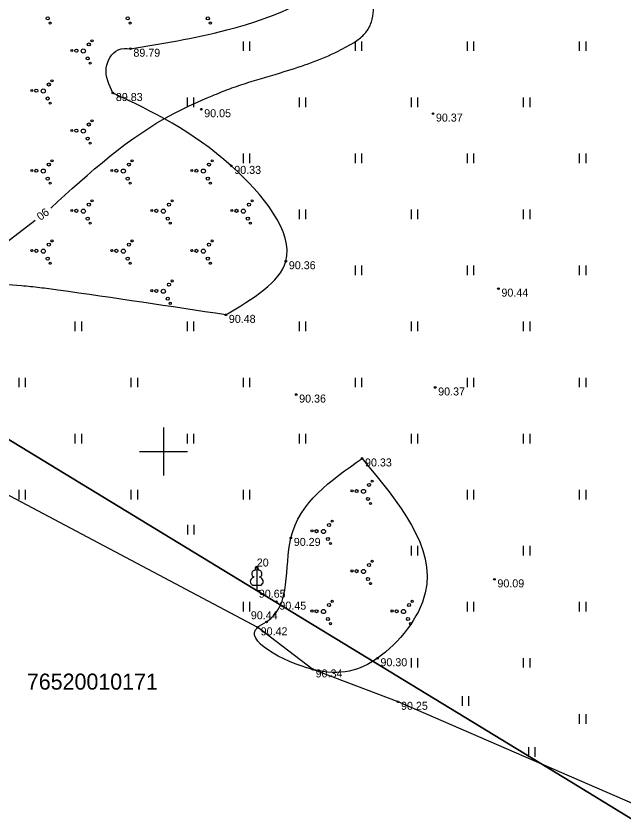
# Model space of a CAD drawing. Extents: x 635228 to 635525, y 248590 to 248800.
# Drawn here: x 635340.8 to 635378.8, y 248626.9 to 248677.2 of the extents above; entities that cross this region are included whole.
import ezdxf

# ---------------------------------------------------------------- set-up
doc = ezdxf.new("R2010")
doc.units = 0
for name, color, linetype in [('GEOD_ELEM_####_####_#', 7, 'Continuous'), ('RAMI_UZMR_####_####_#', 7, 'Continuous'), ('RELJ_AATZ_####_TKST_#', 7, 'Continuous'), ('RELJ_ELEM_####_####_#', 7, 'Continuous'), ('RELJ_HORZ_####_TKST_#', 7, 'Continuous'), ('RELJ_HORZ_RESN_####_#', 7, 'Continuous'), ('RELJ_NOGA_####_####_#', 7, 'Continuous'), ('RELJ_NOGL_####_####_#', 7, 'Continuous'), ('ROBZ_UZMR_####_####_#', 7, 'Continuous'), ('ROBZ_UZMR_####_TKST_#', 7, 'Continuous'), ('TERT_DIAM_####_TKST_#', 7, 'Continuous'), ('TERT_ELEM_####_####_#', 7, 'Continuous'), ('TERT_KONT_####_####_#', 7, 'Continuous')]:
    doc.layers.add(name, color=color, linetype=linetype)

msp = doc.modelspace()

# ---------------------------------------------------------------- linework, layer by layer
at = {"layer": 'GEOD_ELEM_####_####_#'}
for p, q in [((635350, 248651.5), (635350, 248650)), ((635348.5, 248650), (635350, 248650)), ((635350, 248650), (635350, 248648.5)), ((635350, 248650), (635351.5, 248650))]:
    msp.add_line(p, q, dxfattribs=at)
at = {"layer": 'RAMI_UZMR_####_####_#'}
msp.add_lwpolyline([(635379.918, 248627.738), (635364.657, 248634.365), (635359.326, 248636.387), (635355.893, 248639.014), (635323.971, 248655.917), (635326.8, 248663.851), (635331.354, 248676.262), (635327.703, 248680.035), (635326.374, 248681.182), (635325.201, 248682.696), (635327.977, 248685.285), (635332.779, 248692.762), (635338.144, 248706.864), (635340.529, 248716.56), (635346.791, 248738.298), (635351.394, 248755.812), (635352.126, 248761.775)], dxfattribs=at)
at = {"layer": 'RELJ_ELEM_####_####_#'}
for centre in [(635347.944, 248675.14), (635346.848, 248672.375), (635352.366, 248671.364), (635366.837, 248671.092), (635354.244, 248667.827), (635357.651, 248661.873), (635370.928, 248660.162), (635353.903, 248658.524), (635366.978, 248653.992), (635358.297, 248653.548), (635362.409, 248649.56), (635357.961, 248644.598), (635370.678, 248642.01), (635357.062, 248640.618), (635356.442, 248639.354), (635355.893, 248639.014), (635363.372, 248637.085), (635359.326, 248636.387), (635364.657, 248634.365)]:
    msp.add_circle(centre, 0.05, dxfattribs=at)
at = {"layer": 'RELJ_HORZ_RESN_####_#'}
msp.add_line((635328.081, 248653.741), (635341.998, 248664.444), dxfattribs=at)
msp.add_spline([(635342.967, 248665.189), (635350.649, 248671.097), (635353.044, 248672.199), (635354.147, 248672.641), (635355.27, 248673.022), (635357.544, 248673.711), (635360.916, 248674.993), (635361.461, 248675.281), (635362, 248675.6), (635362.585, 248676.091), (635362.941, 248676.666), (635363.082, 248678.034), (635362.825, 248678.873), (635362.542, 248679.71), (635361.896, 248681.359), (635361.504, 248682.258), (635361.094, 248683.142), (635360.687, 248684.033), (635360.306, 248684.949), (635359.942, 248686.647), (635360.049, 248687.813), (635360.176, 248688.176), (635361.529, 248691.159), (635363.072, 248694.104), (635364.881, 248696.95), (635367.032, 248699.635), (635368.378, 248700.848), (635369.286, 248701.486)], degree=3, dxfattribs=at)
at = {"layer": 'RELJ_NOGA_####_####_#'}
for points in [[(635375.27, 248754.857), (635369.314, 248744.971), (635367.429, 248741.507), (635365.696, 248737.957), (635363.943, 248734.417), (635363.006, 248732.681), (635362, 248730.984), (635361.355, 248730.103), (635360.628, 248729.283), (635359.885, 248728.474), (635359.193, 248727.625), (635357.58, 248725.368), (635356.018, 248723.079), (635353.089, 248718.349), (635349.569, 248710.638), (635349.163, 248709.221), (635348.864, 248707.772), (635348.539, 248706.335), (635348.053, 248704.954), (635343.12, 248694.162), (635337.407, 248681.667), (635331.093, 248670.147), (635326.8, 248663.851)], [(635326.8, 248663.851), (635325.31, 248661.345), (635325.174, 248660.918), (635325.219, 248660.451), (635325.416, 248659.984), (635325.736, 248659.553), (635326.126, 248659.27), (635326.575, 248659.146), (635327.409, 248659.333), (635327.907, 248659.688), (635328.397, 248660.078), (635328.864, 248660.506), (635329.288, 248660.978), (635331.594, 248663.918), (635332.687, 248665.412), (635333.734, 248666.95), (635337.875, 248673.353), (635341.554, 248680.001), (635347.428, 248693.006), (635353.063, 248706.101), (635354.098, 248708.621), (635355.097, 248711.155), (635356.117, 248713.682), (635356.653, 248714.935), (635357.216, 248716.179), (635358.916, 248719.218), (635360.822, 248722.14), (635362.339, 248724.363), (635363.916, 248726.545), (635365.467, 248728.744), (635366.906, 248731.015), (635368.464, 248733.981), (635369.863, 248737.03), (635371.249, 248740.086), (635372.769, 248743.072), (635378.435, 248753.196)]]:
    msp.add_spline(points, degree=3, dxfattribs=at)
at = {"layer": 'RELJ_NOGL_####_####_#'}
msp.add_spline([(635326.936, 248660.713), (635331.766, 248667.928), (635333.88, 248671.254), (635335.853, 248674.668), (635337.706, 248678.153), (635339.464, 248681.691), (635342.12, 248687.391), (635344.65, 248693.14), (635347.108, 248698.916), (635349.548, 248704.698), (635350.777, 248707.84), (635351.91, 248711.022), (635353.067, 248714.195), (635353.692, 248715.764), (635354.368, 248717.312), (635355.034, 248718.536), (635355.835, 248719.677), (635357.677, 248721.811), (635359.567, 248723.919), (635361.176, 248726.206), (635362.355, 248728.434), (635362.939, 248729.551), (635363.546, 248730.656), (635367.422, 248737.348), (635371.307, 248744.035), (635372.506, 248746.487), (635373.579, 248749.023), (635374.785, 248751.459), (635376.384, 248753.612), (635376.807, 248754.05)], degree=3, dxfattribs=at)
at = {"layer": 'ROBZ_UZMR_####_####_#'}
msp.add_lwpolyline([(635325.542, 248659.74), (635329.653, 248676.366), (635327.79, 248676.828), (635337.46, 248688.66), (635343.343, 248703.12), (635360.483, 248762.615), (635458.607, 248711.134), (635465.459, 248707.539), (635439.457, 248681.038), (635424.543, 248670.014), (635420.979, 248667.379), (635407.07, 248653.18), (635400.067, 248641.149), (635395.162, 248617.539), (635389.031, 248621.062), (635375.858, 248629.115)], close=True, dxfattribs=at)
msp.add_lwpolyline([(635385.967, 248592.676), (635383.57, 248593.46), (635239.492, 248640.545), (635247.631, 248661.649), (635302.855, 248630.558), (635325.542, 248659.74), (635375.858, 248629.115), (635389.031, 248621.062), (635395.162, 248617.539), (635393.88, 248601.96), (635390.766, 248592.676)], dxfattribs=at)
at = {"layer": 'TERT_ELEM_####_####_#'}
for p, q in [((635355, 248675), (635355, 248675.6)), ((635355.4, 248675), (635355.4, 248675.6)), ((635362, 248675), (635362, 248675.6)), ((635362.4, 248675), (635362.4, 248675.6)), ((635369, 248675), (635369, 248675.6)), ((635369.4, 248675), (635369.4, 248675.6)), ((635376, 248675), (635376, 248675.6)), ((635376.4, 248675), (635376.4, 248675.6)), ((635351.5, 248671.5), (635351.5, 248672.1)), ((635351.9, 248671.5), (635351.9, 248672.1)), ((635358.5, 248671.5), (635358.5, 248672.1)), ((635358.9, 248671.5), (635358.9, 248672.1)), ((635365.5, 248671.5), (635365.5, 248672.1)), ((635365.9, 248671.5), (635365.9, 248672.1)), ((635372.5, 248671.5), (635372.5, 248672.1)), ((635372.9, 248671.5), (635372.9, 248672.1)), ((635355, 248668), (635355, 248668.6)), ((635355.4, 248668), (635355.4, 248668.6)), ((635362, 248668), (635362, 248668.6)), ((635362.4, 248668), (635362.4, 248668.6)), ((635369, 248668), (635369, 248668.6)), ((635369.4, 248668), (635369.4, 248668.6)), ((635376, 248668), (635376, 248668.6)), ((635376.4, 248668), (635376.4, 248668.6)), ((635358.5, 248664.5), (635358.5, 248665.1)), ((635358.9, 248664.5), (635358.9, 248665.1)), ((635365.5, 248664.5), (635365.5, 248665.1)), ((635365.9, 248664.5), (635365.9, 248665.1)), ((635372.5, 248664.5), (635372.5, 248665.1)), ((635372.9, 248664.5), (635372.9, 248665.1)), ((635362, 248661), (635362, 248661.6)), ((635362.4, 248661), (635362.4, 248661.6)), ((635369, 248661), (635369, 248661.6)), ((635369.4, 248661), (635369.4, 248661.6)), ((635376, 248661), (635376, 248661.6)), ((635376.4, 248661), (635376.4, 248661.6)), ((635344.5, 248657.5), (635344.5, 248658.1)), ((635344.9, 248657.5), (635344.9, 248658.1)), ((635351.5, 248657.5), (635351.5, 248658.1)), ((635351.9, 248657.5), (635351.9, 248658.1)), ((635358.5, 248657.5), (635358.5, 248658.1)), ((635358.9, 248657.5), (635358.9, 248658.1)), ((635365.5, 248657.5), (635365.5, 248658.1)), ((635365.9, 248657.5), (635365.9, 248658.1)), ((635372.5, 248657.5), (635372.5, 248658.1)), ((635372.9, 248657.5), (635372.9, 248658.1)), ((635341, 248654), (635341, 248654.6)), ((635341.4, 248654), (635341.4, 248654.6)), ((635348, 248654), (635348, 248654.6)), ((635348.4, 248654), (635348.4, 248654.6)), ((635355, 248654), (635355, 248654.6)), ((635355.4, 248654), (635355.4, 248654.6)), ((635362, 248654), (635362, 248654.6)), ((635362.4, 248654), (635362.4, 248654.6)), ((635369, 248654), (635369, 248654.6)), ((635369.4, 248654), (635369.4, 248654.6)), ((635376, 248654), (635376, 248654.6)), ((635376.4, 248654), (635376.4, 248654.6)), ((635344.5, 248650.5), (635344.5, 248651.1)), ((635344.9, 248650.5), (635344.9, 248651.1)), ((635351.5, 248650.5), (635351.5, 248651.1)), ((635351.9, 248650.5), (635351.9, 248651.1)), ((635358.5, 248650.5), (635358.5, 248651.1)), ((635358.9, 248650.5), (635358.9, 248651.1)), ((635365.5, 248650.5), (635365.5, 248651.1)), ((635365.9, 248650.5), (635365.9, 248651.1)), ((635372.5, 248650.5), (635372.5, 248651.1)), ((635372.9, 248650.5), (635372.9, 248651.1)), ((635341, 248647), (635341, 248647.6)), ((635341.4, 248647), (635341.4, 248647.6)), ((635348, 248647), (635348, 248647.6)), ((635348.4, 248647), (635348.4, 248647.6)), ((635355, 248647), (635355, 248647.6)), ((635355.4, 248647), (635355.4, 248647.6)), ((635369, 248647), (635369, 248647.6)), ((635369.4, 248647), (635369.4, 248647.6)), ((635376, 248647), (635376, 248647.6)), ((635376.4, 248647), (635376.4, 248647.6)), ((635351.529, 248644.812), (635351.529, 248645.412)), ((635351.929, 248644.812), (635351.929, 248645.412)), ((635365.5, 248643.5), (635365.5, 248644.1)), ((635365.9, 248643.5), (635365.9, 248644.1)), ((635372.5, 248643.5), (635372.5, 248644.1)), ((635372.9, 248643.5), (635372.9, 248644.1)), ((635355.835, 248641.657), (635355.835, 248641.31)), ((635355.835, 248641.31), (635356.035, 248641.31)), ((635355, 248640), (635355, 248640.6)), ((635355.4, 248640), (635355.4, 248640.6)), ((635369, 248640), (635369, 248640.6)), ((635369.4, 248640), (635369.4, 248640.6)), ((635376, 248640), (635376, 248640.6)), ((635376.4, 248640), (635376.4, 248640.6)), ((635365.5, 248636.5), (635365.5, 248637.1)), ((635365.9, 248636.5), (635365.9, 248637.1)), ((635372.5, 248636.5), (635372.5, 248637.1)), ((635372.9, 248636.5), (635372.9, 248637.1)), ((635368.683, 248634.11), (635368.683, 248634.71)), ((635369.083, 248634.11), (635369.083, 248634.71)), ((635376, 248633), (635376, 248633.6)), ((635376.4, 248633), (635376.4, 248633.6)), ((635372.827, 248630.928), (635372.827, 248631.528)), ((635373.227, 248630.928), (635373.227, 248631.528))]:
    msp.add_line(p, q, dxfattribs=at)
for points in [[(635355.835, 248642.81), (635355.835, 248641.657)], [(635355.925, 248642.578), (635355.924, 248642.579)]]:
    msp.add_lwpolyline(points, dxfattribs=at)
for centre, radius in [((635342.776, 248677.033), 0.096), ((635347.776, 248677.033), 0.096), ((635352.776, 248677.033), 0.096), ((635342.934, 248676.744), 0.064), ((635347.934, 248676.744), 0.064), ((635352.934, 248676.744), 0.064), ((635345.544, 248675.639), 0.064), ((635344.282, 248675.034), 0.064), ((635344.566, 248675.021), 0.096), ((635345, 248675), 0.128), ((635345.348, 248675.408), 0.096), ((635345.276, 248674.533), 0.096), ((635345.434, 248674.244), 0.064), ((635343.044, 248673.139), 0.064), ((635341.782, 248672.534), 0.064), ((635342.066, 248672.521), 0.096), ((635342.5, 248672.5), 0.128), ((635342.848, 248672.908), 0.096), ((635342.776, 248672.033), 0.096), ((635342.934, 248671.744), 0.064), ((635345.544, 248670.639), 0.064), ((635344.282, 248670.034), 0.064), ((635344.566, 248670.021), 0.096), ((635345, 248670), 0.128), ((635345.348, 248670.408), 0.096), ((635345.276, 248669.533), 0.096), ((635345.434, 248669.244), 0.064), ((635343.044, 248668.139), 0.064), ((635348.044, 248668.139), 0.064), ((635353.044, 248668.139), 0.064), ((635341.782, 248667.534), 0.064), ((635342.066, 248667.521), 0.096), ((635342.5, 248667.5), 0.128), ((635342.848, 248667.908), 0.096), ((635346.782, 248667.534), 0.064), ((635347.066, 248667.521), 0.096), ((635347.5, 248667.5), 0.128), ((635347.848, 248667.908), 0.096), ((635351.782, 248667.534), 0.064), ((635352.066, 248667.521), 0.096), ((635352.5, 248667.5), 0.128), ((635352.848, 248667.908), 0.096), ((635342.776, 248667.033), 0.096), ((635347.776, 248667.033), 0.096), ((635352.776, 248667.033), 0.096), ((635342.934, 248666.744), 0.064), ((635347.934, 248666.744), 0.064), ((635352.934, 248666.744), 0.064), ((635345.544, 248665.639), 0.064), ((635350.544, 248665.639), 0.064), ((635355.544, 248665.639), 0.064), ((635344.282, 248665.034), 0.064), ((635344.566, 248665.021), 0.096), ((635345, 248665), 0.128), ((635345.348, 248665.408), 0.096), ((635349.282, 248665.034), 0.064), ((635349.566, 248665.021), 0.096), ((635350, 248665), 0.128), ((635350.348, 248665.408), 0.096), ((635354.282, 248665.034), 0.064), ((635354.566, 248665.021), 0.096), ((635355, 248665), 0.128), ((635355.348, 248665.408), 0.096), ((635345.276, 248664.533), 0.096), ((635350.276, 248664.533), 0.096), ((635355.276, 248664.533), 0.096), ((635345.434, 248664.244), 0.064), ((635350.434, 248664.244), 0.064), ((635355.434, 248664.244), 0.064), ((635343.044, 248663.139), 0.064), ((635348.044, 248663.139), 0.064), ((635353.044, 248663.139), 0.064), ((635341.782, 248662.534), 0.064), ((635342.066, 248662.521), 0.096), ((635342.5, 248662.5), 0.128), ((635342.848, 248662.908), 0.096), ((635346.782, 248662.534), 0.064), ((635347.066, 248662.521), 0.096), ((635347.5, 248662.5), 0.128), ((635347.848, 248662.908), 0.096), ((635351.782, 248662.534), 0.064), ((635352.066, 248662.521), 0.096), ((635352.5, 248662.5), 0.128), ((635352.848, 248662.908), 0.096), ((635342.776, 248662.033), 0.096), ((635347.776, 248662.033), 0.096), ((635352.776, 248662.033), 0.096), ((635342.934, 248661.744), 0.064), ((635347.934, 248661.744), 0.064), ((635352.934, 248661.744), 0.064), ((635350.544, 248660.639), 0.064), ((635349.282, 248660.034), 0.064), ((635349.566, 248660.021), 0.096), ((635350, 248660), 0.128), ((635350.348, 248660.408), 0.096), ((635350.276, 248659.533), 0.096), ((635350.434, 248659.244), 0.064), ((635362.848, 248647.908), 0.096), ((635363.044, 248648.139), 0.064), ((635361.782, 248647.534), 0.064), ((635362.066, 248647.521), 0.096), ((635362.5, 248647.5), 0.128), ((635362.776, 248647.033), 0.096), ((635362.934, 248646.744), 0.064), ((635360.348, 248645.408), 0.096), ((635360.544, 248645.639), 0.064), ((635359.282, 248645.034), 0.064), ((635359.566, 248645.021), 0.096), ((635360, 248645), 0.128), ((635360.276, 248644.533), 0.096), ((635360.434, 248644.244), 0.064), ((635362.848, 248642.908), 0.096), ((635363.044, 248643.139), 0.064), ((635361.782, 248642.534), 0.064), ((635362.066, 248642.521), 0.096), ((635362.5, 248642.5), 0.128), ((635362.776, 248642.033), 0.096), ((635362.934, 248641.744), 0.064), ((635360.348, 248640.408), 0.096), ((635360.544, 248640.639), 0.064), ((635365.348, 248640.408), 0.096), ((635365.544, 248640.639), 0.064), ((635359.282, 248640.034), 0.064), ((635359.566, 248640.021), 0.096), ((635360, 248640), 0.128), ((635364.282, 248640.034), 0.064), ((635364.566, 248640.021), 0.096), ((635365, 248640), 0.128), ((635360.276, 248639.533), 0.096), ((635365.276, 248639.533), 0.096), ((635360.434, 248639.244), 0.064), ((635365.434, 248639.244), 0.064)]:
    msp.add_circle(centre, radius, dxfattribs=at)
for centre, major_axis, ratio, start_param, end_param in [((635355.707, 248642.365), (-0.039, -0.212), 0.861323, 3.141593, 6.283185), ((635355.836, 248642.66), (0, -0.15), 0.707107, 3.14537, 5.287485), ((635355.835, 248642.66), (0, -0.15), 0.707107, 0.995701, 3.137816), ((635355.964, 248642.365), (0.039, -0.212), 0.861323, 0, 3.141593), ((635355.746, 248641.903), (0.307, 0.095), 0.814445, 1.570796, 4.752015), ((635355.925, 248641.903), (-0.307, 0.095), 0.814445, 1.531171, 4.712389)]:
    msp.add_ellipse(centre, major_axis=major_axis, ratio=ratio, start_param=start_param, end_param=end_param, dxfattribs=at)
at = {"layer": 'TERT_KONT_####_####_#'}
for points in [[(635347.944, 248675.14), (635353.969, 248676.317), (635361.548, 248680.892), (635362.735, 248687.694), (635367.699, 248695.072), (635365.801, 248699.259), (635373.4, 248711.674), (635374.835, 248703.881), (635382.868, 248697.463), (635386.085, 248703.415)], [(635346.848, 248672.375), (635346.437, 248673.942), (635347.182, 248675.073), (635347.944, 248675.14)], [(635353.903, 248658.524), (635357.651, 248661.873), (635354.244, 248667.827), (635346.848, 248672.375)], [(635353.903, 248658.524), (635343.418, 248660.068), (635342.282, 248660.217), (635341.143, 248660.334), (635338.859, 248660.518), (635336.573, 248660.702), (635335.431, 248660.82), (635334.861, 248660.889), (635334.291, 248660.968), (635332.733, 248661.498), (635331.639, 248662.632), (635331.266, 248663.487)], [(635362.409, 248649.56), (635357.961, 248644.598), (635356.442, 248639.354), (635355.893, 248639.014), (635359.326, 248636.387), (635363.372, 248637.085), (635366.354, 248641.172), (635362.409, 248649.56)]]:
    msp.add_spline(points, degree=3, dxfattribs=at)

# ---------------------------------------------------------------- texts
at = {"layer": 'RELJ_AATZ_####_TKST_#'}
for s, p in [(' 89.79', (635347.944, 248674.64)), (' 89.83', (635346.848, 248671.875)), (' 90.05', (635352.366, 248670.864)), (' 90.37', (635366.837, 248670.592)), (' 90.33', (635354.244, 248667.327)), (' 90.36', (635357.651, 248661.373)), (' 90.44', (635370.928, 248659.662)), (' 90.48', (635353.903, 248658.024)), (' 90.37', (635366.978, 248653.492)), (' 90.36', (635358.297, 248653.048)), (' 90.33', (635362.409, 248649.06)), (' 90.29', (635357.961, 248644.098)), (' 90.09', (635370.678, 248641.51)), (' 90.65', (635355.776, 248640.864)), (' 90.45', (635357.062, 248640.118)), (' 90.44', (635355.279, 248639.519)), (' 90.42', (635355.893, 248638.514)), (' 90.30', (635363.372, 248636.585)), (' 90.34', (635359.326, 248635.887)), (' 90.25', (635364.657, 248633.865))]:
    msp.add_text(s, height=0.5, dxfattribs=at).set_placement(p)
at = {"layer": 'RELJ_HORZ_####_TKST_#'}
msp.add_text('90', height=0.5, rotation=217.5616, dxfattribs=at).set_placement((635342.617, 248665.235))
at = {"layer": 'ROBZ_UZMR_####_TKST_#'}
msp.add_text('76520010171', height=1, dxfattribs=at).set_placement((635341.477, 248635.126))
at = {"layer": 'TERT_DIAM_####_TKST_#'}
msp.add_text('20', height=0.5, dxfattribs=at).set_placement((635355.835, 248642.81))

doc.saveas('drawing.dxf')
